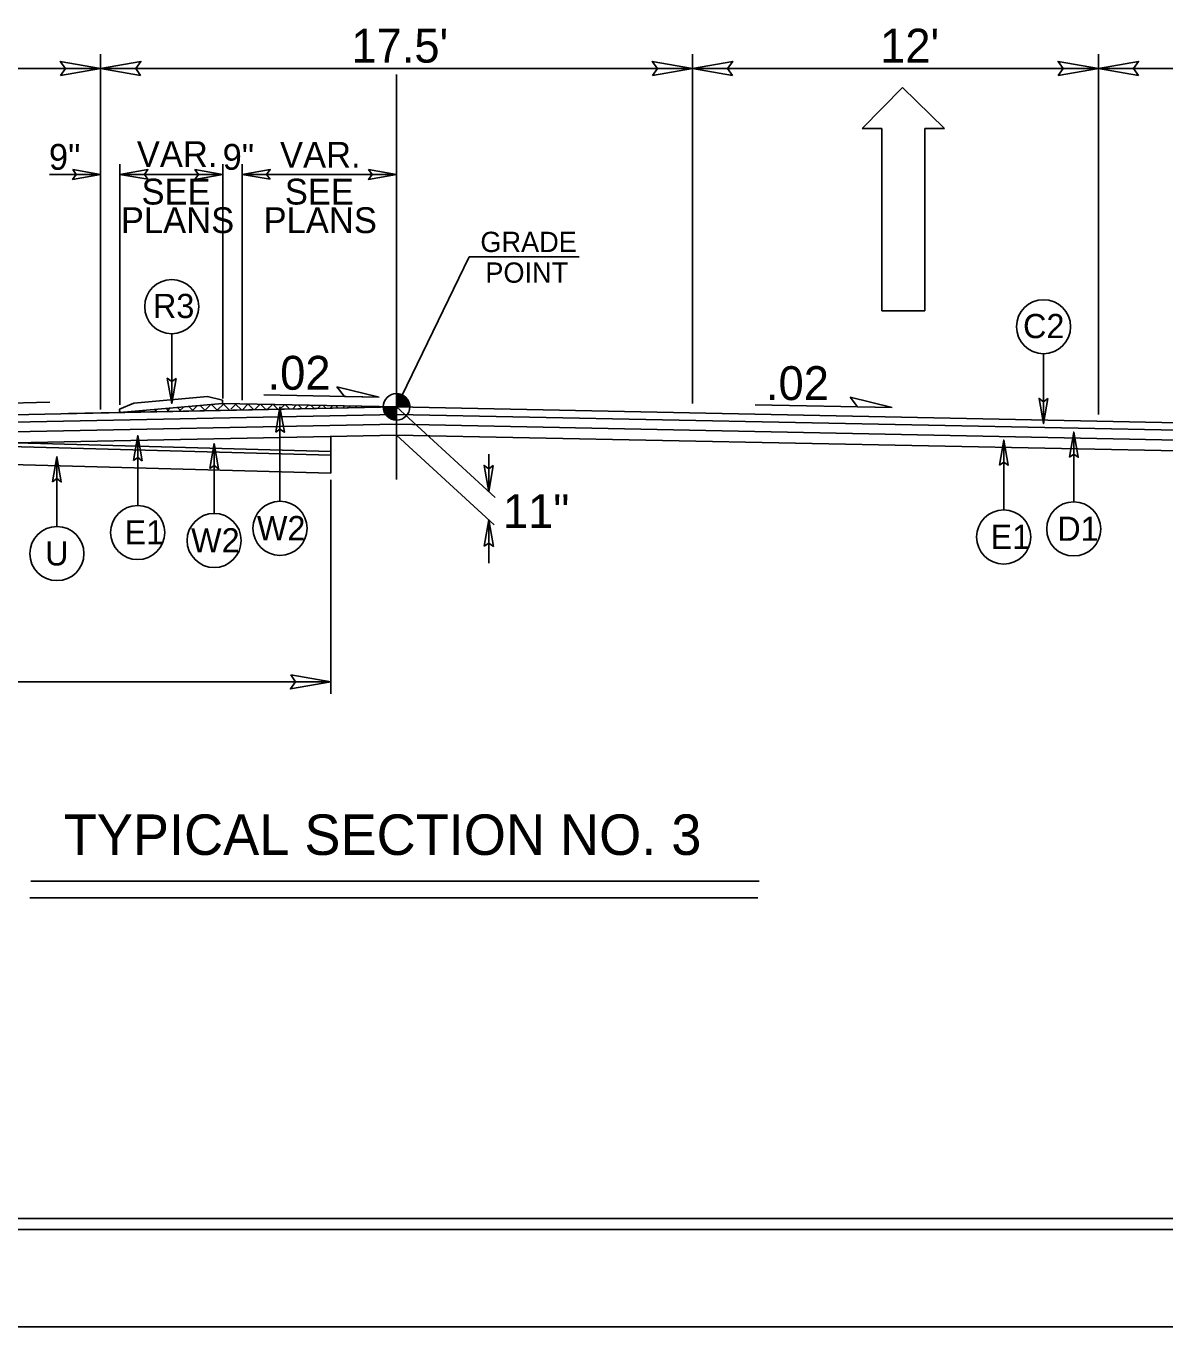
# Model space of a CAD drawing. Extents: x 957297 to 961629, y 830661 to 840840.
# Drawn here: x 959409.2 to 959671.5, y 838515.4 to 838815 of the extents above; entities that cross this region are included whole.
import ezdxf

# ---------------------------------------------------------------- set-up
doc = ezdxf.new("R2010")
doc.units = 0
for name, color, linetype in [('Default', 7, 'Continuous'), ('Old_Level_1', 7, 'Continuous'), ('Old_Level_11', 7, 'Continuous'), ('Old_Level_3', 7, 'Continuous'), ('Prop CMT Pvmt Milling', 7, 'Continuous'), ('Prop Dimension Text', 7, 'Continuous'), ('Prop Lane Arrow CELL', 7, 'Continuous'), ('Sheet Plot Border Inside CELL', 7, 'Continuous'), ('Sheet Plot Border Outside CELL', 7, 'Continuous'), ('Sheet Typical CELL', 7, 'Continuous'), ('Typical ID Circle CELL', 7, 'Continuous'), ('Typical Terminator CELL', 7, 'Continuous'), ('Typical Text Grade Point CELL', 7, 'Continuous'), ('Typical Text ID Circle CELL', 7, 'Continuous')]:
    doc.layers.add(name, color=color, linetype=linetype)

# ---------------------------------------------------------------- blocks, each defined once
blk = doc.blocks.new('Lane Arrow Through')
at = {"layer": 'Prop Lane Arrow CELL'}
for p, q in [((-3.15, 1.6), (-3.15, 3.1)), ((-3.15, 3.1), (0, 0)), ((-17.15, 1.6), (-3.15, 1.6)), ((-17.15, -1.7), (-17.15, 1.6)), ((0, 0), (-3.15, -3.2)), ((-3.15, -1.7), (-17.15, -1.7)), ((-3.15, -3.2), (-3.15, -1.7))]:
    blk.add_line(p, q, dxfattribs=at)

msp = doc.modelspace()

# ---------------------------------------------------------------- linework, layer by layer
at = {"layer": 'Default'}
msp.add_line((959494.54, 838803.85), (959494.54, 838710.55), dxfattribs=at)
at = {"layer": 'Old_Level_1'}
for p, q in [((959426.38, 838808.54), (959426.38, 838726.64)), ((959562.7, 838808.54), (959562.7, 838728.06)), ((959656.18, 838808.54), (959656.18, 838725.5)), ((959332.9, 838805.18), (959426.38, 838805.18)), ((959426.38, 838805.18), (959562.7, 838805.18)), ((959562.7, 838805.18), (959656.18, 838805.18)), ((959656.18, 838805.18), (959749.66, 838805.18)), ((959430.82, 838727.76), (959430.82, 838783.21)), ((959454.53, 838729.21), (959454.53, 838783.21)), ((959458.97, 838728.86), (959458.97, 838783.21)), ((959414.58, 838780.8), (959426.38, 838780.8)), ((959430.82, 838780.8), (959454.53, 838780.8)), ((959458.97, 838780.8), (959494.54, 838780.8)), ((959414.71, 838728.33), (959384.5, 838727.72)), ((959430.82, 838725.98), (959454.48, 838728.08)), ((959454.48, 838728.08), (959494.54, 838727.27)), ((959463.98, 838730.05), (959490.53, 838729.52)), ((959494.54, 838727.27), (959494.54, 838730.34)), ((959494.54, 838727.27), (959494.54, 838730.34)), ((959494.54, 838727.27), (959206.42, 838721.44)), ((959494.54, 838725.54), (959206.42, 838719.71)), ((959494.54, 838727.27), (959418.97, 838725.74)), ((959491.48, 838727.27), (959494.54, 838727.27)), ((959491.48, 838727.27), (959494.54, 838727.27)), ((959494.54, 838727.27), (959517.24, 838706.38)), ((959497.6, 838727.27), (959494.54, 838727.27)), ((959494.54, 838724.22), (959494.54, 838727.27)), ((959494.54, 838727.27), (959494.54, 838724.22)), ((959494.54, 838727.27), (959782.66, 838721.44)), ((959497.6, 838727.27), (959494.54, 838727.27)), ((959494.54, 838724.22), (959494.54, 838727.27)), ((959494.54, 838727.27), (959494.54, 838724.22)), ((959494.54, 838725.54), (959782.66, 838719.72)), ((959577.12, 838727.77), (959608.72, 838727.13)), ((959494.54, 838723.29), (959354.01, 838720.44)), ((959494.54, 838723.29), (959782.66, 838717.46)), ((959494.54, 838720.79), (959406.57, 838719.01)), ((959479.42, 838720.48), (959479.42, 838717.03)), ((959494.54, 838720.79), (959517.05, 838700.08)), ((959494.54, 838720.79), (959805.61, 838714.5)), ((959479.43, 838711.98), (959479.42, 838717.03)), ((959515.78, 838716.4), (959515.79, 838707.72)), ((959479.39, 838710.49), (959479.39, 838661.19)), ((959515.77, 838701.25), (959515.77, 838691.3)), ((959133.56, 838663.97), (959479.39, 838663.97)), ((959578.04, 838618.06), (959410.34, 838618.06)), ((959577.76, 838614.25), (959410.06, 838614.25))]:
    msp.add_line(p, q, dxfattribs=at)
for points in [[(959494.58, 838730.34), (959494.58, 838730.34), (959494.58, 838727.27)], [(959494.58, 838730.34), (959494.58, 838730.34), (959494.58, 838727.27)], [(959494.63, 838730.34), (959494.63, 838727.27)], [(959494.63, 838730.34), (959494.63, 838727.27)], [(959494.69, 838730.33), (959494.69, 838727.27)], [(959494.69, 838730.33), (959494.69, 838727.27)], [(959494.76, 838730.32), (959494.76, 838727.27)], [(959494.76, 838730.32), (959494.76, 838727.27)], [(959494.82, 838730.32), (959494.82, 838727.27)], [(959494.82, 838730.32), (959494.82, 838727.27)], [(959494.88, 838730.32), (959494.88, 838727.27)], [(959494.88, 838730.32), (959494.88, 838727.27)], [(959494.94, 838730.31), (959494.94, 838727.27)], [(959494.94, 838730.31), (959494.94, 838727.27)], [(959495, 838730.31), (959495, 838727.27)], [(959495, 838730.31), (959495, 838727.27)], [(959495.06, 838730.28), (959495.06, 838727.27)], [(959495.06, 838730.28), (959495.06, 838727.27)], [(959495.12, 838730.28), (959495.12, 838727.27)], [(959495.12, 838730.28), (959495.12, 838727.27)], [(959495.19, 838730.27), (959495.19, 838727.27)], [(959495.19, 838730.27), (959495.19, 838727.27)], [(959495.25, 838730.25), (959495.25, 838727.27)], [(959495.25, 838730.25), (959495.25, 838727.27)], [(959495.31, 838730.23), (959495.31, 838727.27)], [(959495.31, 838730.23), (959495.31, 838727.27)], [(959495.37, 838730.22), (959495.37, 838727.27)], [(959495.37, 838730.22), (959495.37, 838727.27)], [(959495.44, 838730.2), (959495.44, 838727.27)], [(959495.44, 838730.2), (959495.44, 838727.27)], [(959495.49, 838730.18), (959495.49, 838727.27)], [(959495.49, 838730.18), (959495.49, 838727.27)], [(959495.56, 838730.16), (959495.55, 838727.27)], [(959495.56, 838730.16), (959495.55, 838727.27)], [(959495.61, 838730.14), (959495.61, 838727.27)], [(959495.61, 838730.14), (959495.61, 838727.27)], [(959495.67, 838730.12), (959495.67, 838727.27)], [(959495.67, 838730.12), (959495.67, 838727.27)], [(959495.74, 838730.09), (959495.74, 838727.27)], [(959495.74, 838730.09), (959495.74, 838727.27)], [(959495.8, 838730.07), (959495.8, 838727.27)], [(959495.8, 838730.07), (959495.8, 838727.27)], [(959495.86, 838730.03), (959495.86, 838727.27)], [(959495.86, 838730.03), (959495.86, 838727.27)], [(959495.91, 838730.01), (959495.91, 838727.27)], [(959495.91, 838730.01), (959495.91, 838727.27)], [(959495.97, 838729.99), (959495.97, 838727.27)], [(959495.97, 838729.99), (959495.97, 838727.27)], [(959496.04, 838729.95), (959496.04, 838727.27)], [(959496.04, 838729.95), (959496.04, 838727.27)], [(959496.1, 838729.91), (959496.1, 838727.27)], [(959496.1, 838729.91), (959496.1, 838727.27)], [(959496.16, 838729.87), (959496.16, 838727.27)], [(959496.16, 838729.87), (959496.16, 838727.27)], [(959496.23, 838729.83), (959496.23, 838727.27)], [(959496.23, 838729.83), (959496.23, 838727.27)], [(959496.29, 838729.78), (959496.29, 838727.27)], [(959496.29, 838729.78), (959496.29, 838727.27)], [(959496.34, 838729.75), (959496.34, 838727.27)], [(959496.34, 838729.75), (959496.34, 838727.27)], [(959496.41, 838729.7), (959496.41, 838727.27)], [(959496.41, 838729.7), (959496.41, 838727.27)], [(959496.47, 838729.65), (959496.47, 838727.27)], [(959496.47, 838729.65), (959496.47, 838727.27)], [(959496.53, 838729.61), (959496.53, 838727.27)], [(959496.53, 838729.61), (959496.53, 838727.27)], [(959496.59, 838729.55), (959496.59, 838727.27)], [(959496.59, 838729.55), (959496.59, 838727.27)], [(959496.65, 838729.49), (959496.65, 838727.27)], [(959496.65, 838729.49), (959496.65, 838727.27)], [(959496.72, 838729.43), (959496.72, 838727.27)], [(959496.72, 838729.43), (959496.72, 838727.27)], [(959496.77, 838729.36), (959496.77, 838727.27)], [(959496.77, 838729.36), (959496.77, 838727.27)], [(959496.83, 838729.3), (959496.83, 838727.27)], [(959496.83, 838729.3), (959496.83, 838727.27)], [(959496.89, 838729.24), (959496.89, 838727.27)], [(959496.89, 838729.24), (959496.89, 838727.27)], [(959496.95, 838729.14), (959496.95, 838727.27)], [(959496.95, 838729.14), (959496.95, 838727.27)], [(959497.02, 838729.07), (959497.02, 838727.27)], [(959497.02, 838729.07), (959497.02, 838727.27)], [(959497.08, 838728.99), (959497.08, 838727.27)], [(959497.08, 838728.99), (959497.08, 838727.27)], [(959497.14, 838728.89), (959497.14, 838727.27)], [(959497.14, 838728.89), (959497.14, 838727.27)], [(959497.2, 838728.79), (959497.2, 838727.27)], [(959497.2, 838728.79), (959497.2, 838727.27)], [(959497.26, 838728.68), (959497.26, 838727.27)], [(959497.26, 838728.68), (959497.26, 838727.27)], [(959497.32, 838728.54), (959497.32, 838727.27)], [(959497.32, 838728.54), (959497.32, 838727.27)], [(959497.39, 838728.39), (959497.39, 838727.27)], [(959497.39, 838728.39), (959497.39, 838727.27)], [(959497.45, 838728.23), (959497.45, 838727.27)], [(959497.45, 838728.23), (959497.45, 838727.27)], [(959497.51, 838728.02), (959497.51, 838727.27)], [(959497.51, 838728.02), (959497.51, 838727.27)], [(959491.5, 838727.27), (959491.5, 838726.95)], [(959491.5, 838727.27), (959491.5, 838726.95)], [(959491.56, 838727.27), (959491.56, 838726.59)], [(959491.56, 838727.27), (959491.56, 838726.59)], [(959491.62, 838727.27), (959491.62, 838726.36)], [(959491.62, 838727.27), (959491.62, 838726.36)], [(959491.68, 838727.27), (959491.68, 838726.18)], [(959491.68, 838727.27), (959491.68, 838726.18)], [(959491.75, 838727.27), (959491.75, 838726.04)], [(959491.75, 838727.27), (959491.75, 838726.04)], [(959491.81, 838727.27), (959491.81, 838725.91)], [(959491.81, 838727.27), (959491.81, 838725.91)], [(959491.87, 838727.27), (959491.87, 838725.8)], [(959491.87, 838727.27), (959491.87, 838725.8)], [(959491.93, 838727.27), (959491.93, 838725.68)], [(959491.93, 838727.27), (959491.93, 838725.68)], [(959492, 838727.27), (959492, 838725.6)], [(959492, 838727.27), (959492, 838725.6)], [(959492.06, 838727.27), (959492.06, 838725.51)], [(959492.06, 838727.27), (959492.06, 838725.51)], [(959492.12, 838727.27), (959492.12, 838725.42)], [(959492.12, 838727.27), (959492.12, 838725.42)], [(959492.18, 838727.27), (959492.18, 838725.35)], [(959492.18, 838727.27), (959492.18, 838725.35)], [(959492.24, 838727.27), (959492.24, 838725.28)], [(959492.24, 838727.27), (959492.24, 838725.28)], [(959492.29, 838727.27), (959492.29, 838725.2)], [(959492.29, 838727.27), (959492.29, 838725.2)], [(959492.35, 838727.27), (959492.35, 838725.13)], [(959492.35, 838727.27), (959492.35, 838725.13)], [(959492.42, 838727.27), (959492.42, 838725.08)], [(959492.42, 838727.27), (959492.42, 838725.08)], [(959492.48, 838727.27), (959492.48, 838725.03)], [(959492.48, 838727.27), (959492.48, 838725.03)], [(959492.54, 838727.27), (959492.54, 838724.97)], [(959492.54, 838727.27), (959492.54, 838724.97)], [(959492.6, 838727.27), (959492.6, 838724.92)], [(959492.6, 838727.27), (959492.6, 838724.92)], [(959492.67, 838727.27), (959492.67, 838724.86)], [(959492.67, 838727.27), (959492.67, 838724.86)], [(959492.72, 838727.27), (959492.72, 838724.82)], [(959492.72, 838727.27), (959492.72, 838724.82)], [(959492.79, 838727.27), (959492.79, 838724.78)], [(959492.79, 838727.27), (959492.79, 838724.78)], [(959492.85, 838727.27), (959492.85, 838724.74)], [(959492.85, 838727.27), (959492.85, 838724.74)], [(959492.91, 838727.27), (959492.91, 838724.69)], [(959492.91, 838727.27), (959492.91, 838724.69)], [(959492.98, 838727.27), (959492.98, 838724.65)], [(959492.98, 838727.27), (959492.98, 838724.65)], [(959493.04, 838727.27), (959493.04, 838724.61)], [(959493.04, 838727.27), (959493.04, 838724.61)], [(959493.1, 838727.27), (959493.1, 838724.58)], [(959493.1, 838727.27), (959493.1, 838724.58)], [(959493.15, 838727.27), (959493.15, 838724.56)], [(959493.15, 838727.27), (959493.15, 838724.56)], [(959493.21, 838727.27), (959493.21, 838724.53)], [(959493.21, 838727.27), (959493.21, 838724.53)], [(959493.28, 838727.27), (959493.28, 838724.49)], [(959493.28, 838727.27), (959493.28, 838724.49)], [(959493.34, 838727.27), (959493.34, 838724.47)], [(959493.34, 838727.27), (959493.34, 838724.47)], [(959493.4, 838727.27), (959493.4, 838724.44)], [(959493.4, 838727.27), (959493.4, 838724.44)], [(959493.46, 838727.27), (959493.46, 838724.42)], [(959493.46, 838727.27), (959493.46, 838724.42)], [(959493.52, 838727.27), (959493.52, 838724.4)], [(959493.52, 838727.27), (959493.52, 838724.4)], [(959493.58, 838727.27), (959493.58, 838724.38)], [(959493.58, 838727.27), (959493.58, 838724.38)], [(959493.64, 838727.27), (959493.64, 838724.36)], [(959493.64, 838727.27), (959493.64, 838724.36)], [(959493.7, 838727.27), (959493.7, 838724.34)], [(959493.7, 838727.27), (959493.7, 838724.34)], [(959493.76, 838727.27), (959493.76, 838724.32)], [(959493.76, 838727.27), (959493.76, 838724.32)], [(959493.83, 838727.27), (959493.83, 838724.31)], [(959493.83, 838727.27), (959493.83, 838724.31)], [(959493.89, 838727.27), (959493.89, 838724.29)], [(959493.89, 838727.27), (959493.89, 838724.29)], [(959493.95, 838727.27), (959493.95, 838724.28)], [(959493.95, 838727.27), (959493.95, 838724.28)], [(959494.01, 838727.27), (959494.01, 838724.28)], [(959494.01, 838727.27), (959494.01, 838724.28)], [(959494.07, 838727.27), (959494.07, 838724.26)], [(959494.07, 838727.27), (959494.07, 838724.26)], [(959494.13, 838727.27), (959494.13, 838724.24)], [(959494.13, 838727.27), (959494.13, 838724.24)], [(959494.2, 838727.27), (959494.2, 838724.24)], [(959494.2, 838727.27), (959494.2, 838724.24)], [(959494.26, 838727.27), (959494.26, 838724.24)], [(959494.26, 838727.27), (959494.26, 838724.24)], [(959494.32, 838727.27), (959494.32, 838724.22)], [(959494.32, 838727.27), (959494.32, 838724.22)], [(959494.38, 838727.27), (959494.38, 838724.22)], [(959494.38, 838727.27), (959494.38, 838724.22)], [(959494.43, 838727.27), (959494.43, 838724.22)], [(959494.43, 838727.27), (959494.43, 838724.22)], [(959494.49, 838727.27), (959494.49, 838724.22), (959494.49, 838724.22)], [(959494.49, 838727.27), (959494.49, 838724.22), (959494.49, 838724.22)], [(959497.57, 838727.72), (959497.57, 838727.27)], [(959497.57, 838727.72), (959497.57, 838727.27)], [(959306.49, 838716.69), (959479.42, 838711.98)]]:
    msp.add_lwpolyline(points, dxfattribs=at)
msp.add_circle((959494.54, 838727.28), 3.06, dxfattribs=at)
msp.add_circle((959494.54, 838727.28), 3.06, dxfattribs=at)
for start, end in [(359.9905, 89.9905), (359.9905, 89.9905), (179.9905, 269.9905), (179.9905, 269.9905)]:
    msp.add_arc((959494.54, 838727.28), 3.06, start, end, dxfattribs=at)
at = {"layer": 'Old_Level_11'}
for p, q in [((959482.53, 838729.67), (959480.8, 838731.93)), ((959480.8, 838731.93), (959490.53, 838729.52)), ((959490.53, 838729.52), (959482.53, 838729.67)), ((959600.72, 838727.29), (959598.99, 838729.55)), ((959598.99, 838729.55), (959608.72, 838727.13)), ((959608.72, 838727.13), (959600.72, 838727.29))]:
    msp.add_line(p, q, dxfattribs=at)
for points in [[(959419.95, 838781.91), (959426.38, 838780.8), (959419.91, 838779.66), (959420.74, 838780.8)], [(959437.25, 838779.69), (959430.82, 838780.8), (959437.28, 838781.94), (959436.46, 838780.8)], [(959448.1, 838781.91), (959454.53, 838780.8), (959448.06, 838779.66), (959448.89, 838780.8)], [(959465.4, 838779.69), (959458.97, 838780.8), (959465.44, 838781.94), (959464.62, 838780.8)], [(959488.11, 838781.91), (959494.54, 838780.8), (959488.08, 838779.66), (959488.9, 838780.8)]]:
    msp.add_lwpolyline(points, close=True, dxfattribs=at)
at = {"layer": 'Old_Level_3'}
for p, q in [((959430.75, 838726.72), (959434, 838728.13)), ((959454.48, 838728.08), (959430.82, 838725.98)), ((959434, 838728.13), (959451.03, 838729.64)), ((959451.03, 838729.64), (959454.46, 838728.82)), ((959453.18, 838726.43), (959454.82, 838728.07)), ((959454.46, 838728.82), (959454.48, 838728.08)), ((959454.51, 838728.08), (959456.1, 838726.49)), ((959456.34, 838726.75), (959457.6, 838728.02)), ((959457.4, 838728.02), (959458.88, 838726.55)), ((959458.97, 838726.55), (959460.38, 838727.96)), ((959460.3, 838727.96), (959461.66, 838726.6)), ((959461.86, 838726.61), (959463.16, 838727.9)), ((959463.19, 838727.9), (959464.44, 838726.66)), ((959430.82, 838725.98), (959430.75, 838726.72)), ((959431.06, 838726), (959431.07, 838725.99)), ((959432.91, 838726.02), (959433.07, 838726.18)), ((959433.66, 838726.23), (959433.85, 838726.04)), ((959435.81, 838726.08), (959436.18, 838726.46)), ((959436.27, 838726.46), (959436.63, 838726.1)), ((959438.7, 838726.14), (959439.3, 838726.73)), ((959438.87, 838726.69), (959439.41, 838726.15)), ((959441.48, 838726.93), (959442.19, 838726.21)), ((959441.6, 838726.2), (959442.41, 838727.01)), ((959444.08, 838727.16), (959444.97, 838726.27)), ((959444.49, 838726.26), (959445.52, 838727.28)), ((959446.69, 838727.39), (959447.75, 838726.32)), ((959447.39, 838726.32), (959448.63, 838727.56)), ((959449.3, 838727.62), (959450.53, 838726.38)), ((959450.28, 838726.37), (959451.75, 838727.84)), ((959451.9, 838727.85), (959453.32, 838726.44)), ((959456.07, 838726.49), (959456.17, 838726.59)), ((959464.76, 838726.67), (959465.94, 838727.85)), ((959466.09, 838727.84), (959467.22, 838726.72)), ((959467.66, 838726.73), (959468.72, 838727.79)), ((959468.99, 838727.78), (959470, 838726.77)), ((959470.55, 838726.78), (959471.5, 838727.73)), ((959471.88, 838727.73), (959472.78, 838726.83)), ((959473.45, 838726.84), (959474.28, 838727.68)), ((959474.78, 838727.67), (959475.56, 838726.88)), ((959476.34, 838726.9), (959477.06, 838727.62)), ((959477.67, 838727.61), (959478.34, 838726.94)), ((959479.24, 838726.96), (959479.84, 838727.57)), ((959480.57, 838727.55), (959481.12, 838727)), ((959482.13, 838727.02), (959482.62, 838727.51)), ((959483.46, 838727.49), (959483.9, 838727.05)), ((959485.03, 838727.08), (959485.4, 838727.45)), ((959486.36, 838727.43), (959486.68, 838727.11)), ((959487.92, 838727.13), (959488.18, 838727.4)), ((959489.25, 838727.38), (959489.46, 838727.17)), ((959490.82, 838727.19), (959490.96, 838727.34)), ((959492.15, 838727.32), (959492.24, 838727.22))]:
    msp.add_line(p, q, dxfattribs=at)
msp.add_lwpolyline([(959430.82, 838725.98), (959454.48, 838728.08), (959494.54, 838727.27)], close=True, dxfattribs=at)
at = {"layer": 'Prop CMT Pvmt Milling'}
msp.add_line((959479.4, 838716.16), (959306.46, 838720.87), dxfattribs=at)
msp.add_lwpolyline([(959306.49, 838721.74), (959479.42, 838717.03)], dxfattribs=at)
at = {"layer": 'Sheet Plot Border Inside CELL'}
msp.add_lwpolyline([(960390.3, 839592.94), (958723.8, 839592.94), (958723.8, 838537.84), (960390.3, 838537.84)], close=True, dxfattribs=at)
at = {"layer": 'Sheet Plot Border Outside CELL'}
msp.add_lwpolyline([(960394.8, 839615.39), (958710.8, 839615.39), (958710.8, 838515.39), (960394.8, 838515.39)], close=True, dxfattribs=at)
at = {"layer": 'Sheet Typical CELL'}
msp.add_lwpolyline([(960377.8, 839590.39), (958877.8, 839590.39), (958877.8, 838540.39), (960377.8, 838540.39)], close=True, dxfattribs=at)
at = {"layer": 'Typical ID Circle CELL'}
for p, q in [((959442.76, 838744.15), (959442.76, 838728.06)), ((959643.55, 838739.51), (959643.55, 838723.42)), ((959467.69, 838705.55), (959467.69, 838727.24)), ((959434.92, 838704.57), (959434.92, 838720.66)), ((959634.38, 838703.54), (959634.38, 838719.63)), ((959650.51, 838705.41), (959650.51, 838721.49)), ((959452.53, 838702.73), (959452.53, 838718.82)), ((959416.31, 838699.72), (959416.31, 838715.81))]:
    msp.add_line(p, q, dxfattribs=at)
for centre in [(959442.76, 838750.37), (959643.55, 838745.74), (959434.92, 838698.35), (959467.69, 838699.32), (959650.51, 838699.18), (959452.53, 838696.51), (959634.38, 838697.32), (959416.31, 838693.5)]:
    msp.add_circle(centre, 6.23, dxfattribs=at)
at = {"layer": 'Typical Terminator CELL'}
for points in [[(959417.15, 838803.59), (959426.38, 838805.18), (959417.1, 838806.82), (959418.28, 838805.18)], [(959435.6, 838803.59), (959426.38, 838805.18), (959435.65, 838806.82), (959434.47, 838805.18)], [(959553.48, 838803.59), (959562.7, 838805.18), (959553.43, 838806.82), (959554.61, 838805.18)], [(959571.92, 838803.59), (959562.7, 838805.18), (959571.98, 838806.82), (959570.8, 838805.18)], [(959646.96, 838803.59), (959656.18, 838805.18), (959646.91, 838806.82), (959648.09, 838805.18)], [(959665.4, 838803.59), (959656.18, 838805.18), (959665.46, 838806.82), (959664.28, 838805.18)], [(959443.75, 838733.83), (959442.76, 838728.06), (959441.74, 838733.86), (959442.76, 838733.12)], [(959644.54, 838729.19), (959643.55, 838723.42), (959642.52, 838729.22), (959643.55, 838728.48)], [(959466.7, 838721.47), (959467.69, 838727.24), (959468.71, 838721.44), (959467.69, 838722.18)], [(959433.93, 838714.9), (959434.92, 838720.66), (959435.94, 838714.86), (959434.92, 838715.6)], [(959633.39, 838713.87), (959634.38, 838719.63), (959635.4, 838713.84), (959634.38, 838714.57)], [(959649.52, 838715.73), (959650.51, 838721.49), (959651.54, 838715.7), (959650.51, 838716.43)], [(959451.54, 838713.06), (959452.53, 838718.82), (959453.56, 838713.02), (959452.53, 838713.76)], [(959415.31, 838710.05), (959416.31, 838715.81), (959417.33, 838710.01), (959416.31, 838710.75)], [(959516.83, 838713.79), (959515.79, 838707.72), (959514.71, 838713.82), (959515.78, 838713.04)], [(959514.72, 838695.19), (959515.77, 838701.25), (959516.85, 838695.15), (959515.77, 838695.93)], [(959470.16, 838665.56), (959479.39, 838663.97), (959470.11, 838662.33), (959471.29, 838663.97)]]:
    msp.add_lwpolyline(points, close=True, dxfattribs=at)
at = {"layer": 'Typical Text Grade Point CELL'}
for q in [(959494.54, 838727.26), (959536.58, 838761.83)]:
    msp.add_line((959511.25, 838761.83), q, dxfattribs=at)

# ---------------------------------------------------------------- block references
at = {"layer": 'Old_Level_1', "xscale": 3, "yscale": 3, "rotation": 90}
msp.add_blockref('Lane Arrow Through', (959611.11, 838800.87), dxfattribs=at)

# ---------------------------------------------------------------- texts
at = {"layer": 'Old_Level_1'}
msp.add_text('TYPICAL SECTION NO. 3', height=9.3239, dxfattribs=at).set_placement((959417.88, 838624.1))
at = {"layer": 'Old_Level_11'}
for s, p in [('GRADE', (959513.85, 838762.94)), ('POINT', (959514.99, 838755.87))]:
    msp.add_text(s, height=4.671, dxfattribs=at).set_placement(p)
at = {"layer": 'Old_Level_3'}
for s, p in [('9"', (959414.47, 838781.88)), ('VAR.', (959434.72, 838782.52)), ('9"', (959454.48, 838781.88)), ('VAR.', (959467.7, 838782.36)), ('SEE', (959435.8, 838773.88)), ('SEE', (959468.81, 838773.88)), ('PLANS', (959431.05, 838767.3)), ('PLANS', (959463.92, 838767.3))]:
    msp.add_text(s, height=5.951, rotation=0, dxfattribs=at).set_placement(p)
at = {"layer": 'Prop Dimension Text'}
for s, rotation, p in [("17.5'", 0, (959484.14, 838806.56)), ("12'", 0, (959605.92, 838806.56)), ('.02', 360, (959464.84, 838731.23)), ('.02', 360, (959579.63, 838728.85)), ('11"', 0, (959519.04, 838699.36))]:
    msp.add_text(s, height=7.801, rotation=rotation, dxfattribs=at).set_placement(p)
at = {"layer": 'Typical Text ID Circle CELL'}
for s, height, p in [('R3', 5.572, (959438.44, 838747.74)), ('C2', 5.572, (959638.84, 838743.11)), ('E1', 5.572, (959431.89, 838695.61)), ('W2', 5.572, (959462.38, 838696.58)), ('D1', 5.572, (959646.72, 838696.44)), ('W2', 5.572, (959447.22, 838693.77)), ('E1', 5.572, (959631.35, 838694.58)), ('U', 5.57, (959413.6, 838690.76))]:
    msp.add_text(s, height=height, dxfattribs=at).set_placement(p)

doc.saveas('drawing.dxf')
